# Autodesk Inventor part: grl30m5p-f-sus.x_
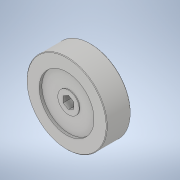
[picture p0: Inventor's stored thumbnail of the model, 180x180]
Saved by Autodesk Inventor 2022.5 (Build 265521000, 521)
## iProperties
Created: 2021-02
Part Number: grl30m5p-f-sus.x_
Material: 一般
Document SubType Name: Modeling
Designer: ImaoCorp
Density: 1 g/cm^3
Appearance: 既定
Sending System: SOLIDWORKS 2019-2019304
MC: AMD64
MC_MODEL: Intel64 Family 6 Model 60 Stepping 3, GenuineIntel
OS: Windows_NT
FRU: Parasolid Version 31.0, build 290,  9- 1-2019
FORMAT: text
GUISE: transmit
KEY: grl30m5p-f-sus
FILE: grl30m5p-f-sus.x_t
DATE: Mon Feb 22 15:02:27 2021
Author: ImaoCorp
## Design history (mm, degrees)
feature "Base1"
node "ソリッド1"
